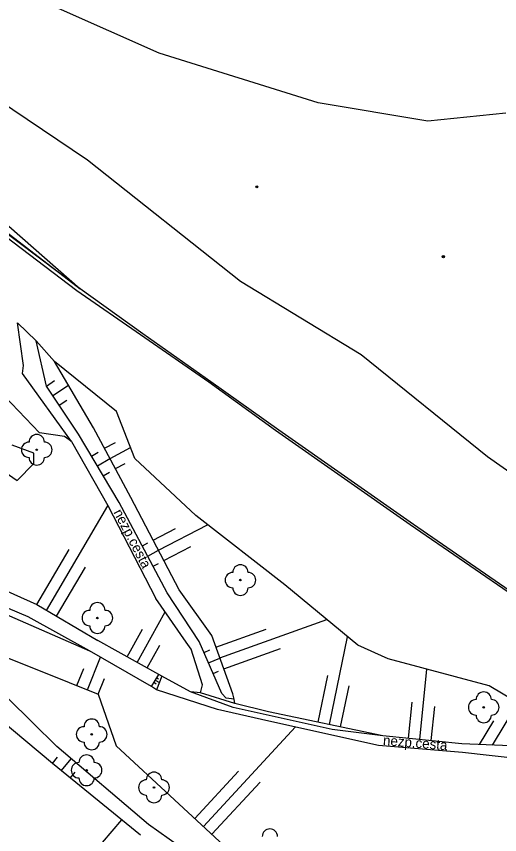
# Model space of a CAD drawing. Extents: x -639440 to -639026, y -1138850 to -1138262.
# Drawn here: x -639194.2 to -639162.7, y -1138656 to -1138602.7 of the extents above; entities that cross this region are included whole.
import ezdxf

# ---------------------------------------------------------------- set-up
doc = ezdxf.new("R2010")
doc.units = 0
for name, color, linetype in [('Vrstva 10', 7, 'Continuous'), ('Vrstva 11', 7, 'Continuous'), ('Vrstva 14', 7, 'Continuous'), ('Vrstva 15', 7, 'Continuous'), ('Vrstva 20', 7, 'Continuous'), ('Vrstva 22', 7, 'Continuous'), ('Vrstva 40', 7, 'Continuous'), ('Vrstva 7', 7, 'Continuous')]:
    doc.layers.add(name, color=color, linetype=linetype)

msp = doc.modelspace()

# ---------------------------------------------------------------- linework, layer by layer
at = {"layer": 'Vrstva 10'}
msp.add_line((-639192.91, -1138623.8), (-639194.14, -1138622.62), dxfattribs=at)
at = {"layer": 'Vrstva 11'}
for p, q in [((-639184.91, -1138605.05), (-639191.46, -1138602.15)), ((-639174.55, -1138608.29), (-639184.91, -1138605.05)), ((-639196.95, -1138607.03), (-639189.58, -1138612.02)), ((-639167.4, -1138609.48), (-639174.55, -1138608.29)), ((-639162.32, -1138608.96), (-639167.4, -1138609.48)), ((-639189.58, -1138612.02), (-639179.6, -1138619.92)), ((-639179.6, -1138619.92), (-639171.74, -1138624.69)), ((-639193.75, -1138625.41), (-639194.14, -1138622.62)), ((-639171.74, -1138624.69), (-639163.51, -1138631.34)), ((-639193.81, -1138625.92), (-639193.75, -1138625.41)), ((-639190.62, -1138630.37), (-639193.81, -1138625.92)), ((-639190.62, -1138630.37), (-639188.25, -1138634.54)), ((-639163.51, -1138631.34), (-639154.27, -1138637.86)), ((-639188.25, -1138634.54), (-639185.12, -1138640.58)), ((-639193.43, -1138641.79), (-639198.66, -1138639.56)), ((-639181.48, -1138643), (-639183.59, -1138640.03)), ((-639183.15, -1138643.44), (-639185.12, -1138640.58)), ((-639189.45, -1138644), (-639193.43, -1138641.79)), ((-639180.11, -1138646.79), (-639181.48, -1138643)), ((-639182.82, -1138643.89), (-639183.15, -1138643.44)), ((-639185.41, -1138646.32), (-639189.45, -1138644)), ((-639182.07, -1138646.22), (-639182.82, -1138643.89)), ((-639185.07, -1138646.54), (-639185.41, -1138646.32)), ((-639182.21, -1138646.74), (-639182.07, -1138646.22)), ((-639181.1, -1138647.81), (-639185.07, -1138646.54)), ((-639180.08, -1138647.68), (-639182.86, -1138646.67)), ((-639180.02, -1138647.15), (-639180.11, -1138646.79)), ((-639191.57, -1138650.23), (-639194.74, -1138647.11)), ((-639179.98, -1138647.42), (-639180.02, -1138647.15)), ((-639177.76, -1138648.57), (-639181.1, -1138647.81)), ((-639173.64, -1138649.12), (-639180.08, -1138647.68)), ((-639170.61, -1138650.17), (-639177.76, -1138648.57)), ((-639170.33, -1138649.53), (-639173.64, -1138649.12)), ((-639185.6, -1138655.32), (-639191.57, -1138650.23)), ((-639165.14, -1138650.62), (-639170.61, -1138650.17)), ((-639161, -1138651.09), (-639165.14, -1138650.62)), ((-639174.79, -1138662.91), (-639185.6, -1138655.32))]:
    msp.add_line(p, q, dxfattribs=at)
at = {"layer": 'Vrstva 14'}
for p, q in [((-639204.07, -1138608.17), (-639190.04, -1138620.41)), ((-639205.13, -1138608.87), (-639190.04, -1138620.41)), ((-639192.7, -1138629.79), (-639198.81, -1138623.41)), ((-639191.72, -1138625.14), (-639192.91, -1138623.8)), ((-639192.25, -1138626.75), (-639192.91, -1138623.8)), ((-639187.69, -1138628.41), (-639191.72, -1138625.14)), ((-639189.18, -1138629.46), (-639191.72, -1138625.14)), ((-639190.16, -1138629.89), (-639192.25, -1138626.75)), ((-639186.49, -1138631.47), (-639187.69, -1138628.41)), ((-639199.22, -1138629.4), (-639194.15, -1138632.91)), ((-639191.07, -1138630.04), (-639192.7, -1138629.79)), ((-639187.5, -1138634.34), (-639190.16, -1138629.89)), ((-639186.74, -1138634.01), (-639189.18, -1138629.46)), ((-639190.62, -1138630.37), (-639191.07, -1138630.04)), ((-639193.07, -1138631.11), (-639194.49, -1138630.6)), ((-639193.07, -1138631.79), (-639193.07, -1138631.11)), ((-639182.52, -1138635.19), (-639186.49, -1138631.47)), ((-639194.15, -1138632.91), (-639193.07, -1138631.79)), ((-639183.59, -1138640.03), (-639186.74, -1138634.01)), ((-639184.38, -1138640.21), (-639187.5, -1138634.34)), ((-639176.72, -1138639.69), (-639182.52, -1138635.19)), ((-639198.41, -1138638.5), (-639192.88, -1138640.99)), ((-639171.97, -1138643.62), (-639176.72, -1138639.69)), ((-639182.29, -1138643.39), (-639184.38, -1138640.21)), ((-639192.88, -1138640.99), (-639188.89, -1138643.33)), ((-639195, -1138641.56), (-639189.45, -1138644)), ((-639198.98, -1138642.76), (-639192.66, -1138645.31)), ((-639184.93, -1138645.53), (-639188.89, -1138643.33)), ((-639180.81, -1138646.77), (-639182.29, -1138643.39)), ((-639169.99, -1138644.52), (-639171.97, -1138643.62)), ((-639163.4, -1138646.27), (-639169.99, -1138644.52)), ((-639192.66, -1138645.31), (-639188.87, -1138646.82)), ((-639185.41, -1138646.32), (-639184.93, -1138645.53)), ((-639184.73, -1138645.65), (-639185.07, -1138646.54)), ((-639184.73, -1138645.65), (-639184.93, -1138645.53)), ((-639182.86, -1138646.67), (-639184.73, -1138645.65)), ((-639158.06, -1138649.5), (-639163.4, -1138646.27)), ((-639188.87, -1138646.82), (-639187.71, -1138650.18)), ((-639182.21, -1138646.74), (-639182.86, -1138646.67)), ((-639179.98, -1138647.42), (-639182.21, -1138646.74)), ((-639180.54, -1138647.08), (-639180.81, -1138646.77)), ((-639180.02, -1138647.15), (-639180.54, -1138647.08)), ((-639177.78, -1138647.98), (-639179.98, -1138647.42)), ((-639170.33, -1138649.53), (-639177.78, -1138647.98)), ((-639191.85, -1138651.33), (-639195.35, -1138648.43)), ((-639165.18, -1138650.05), (-639170.33, -1138649.53)), ((-639187.71, -1138650.18), (-639174.57, -1138662.33)), ((-639161.13, -1138650.22), (-639165.18, -1138650.05)), ((-639186.12, -1138656), (-639191.85, -1138651.33))]:
    msp.add_line(p, q, dxfattribs=at)
at = {"layer": 'Vrstva 15'}
for p, q in [((-639192.25, -1138626.75), (-639191.719, -1138626.397)), ((-639191.834, -1138627.374), (-639190.808, -1138626.691)), ((-639191.419, -1138627.999), (-639190.923, -1138627.669)), ((-639188.461, -1138630.802), (-639187.755, -1138630.423)), ((-639188.106, -1138631.463), (-639186.773, -1138630.748)), ((-639189.312, -1138631.308), (-639188.887, -1138631.054)), ((-639188.928, -1138631.952), (-639188.107, -1138631.461)), ((-639187.752, -1138632.123), (-639187.125, -1138631.787)), ((-639188.543, -1138632.595), (-639188.147, -1138632.359)), ((-639192.233, -1138641.37), (-639188.239, -1138634.56)), ((-639184.941, -1138637.449), (-639181.756, -1138635.783)), ((-639185.288, -1138636.784), (-639183.848, -1138636.031)), ((-639192.88, -1138640.99), (-639190.773, -1138637.398)), ((-639186, -1138637.162), (-639185.644, -1138636.973)), ((-639184.593, -1138638.114), (-639182.849, -1138637.201)), ((-639185.648, -1138637.824), (-639184.941, -1138637.448)), ((-639185.296, -1138638.486), (-639184.945, -1138638.299)), ((-639191.586, -1138641.749), (-639189.709, -1138638.548)), ((-639186.338, -1138644.748), (-639184.513, -1138641.462)), ((-639180.95, -1138644.465), (-639173.99, -1138641.949)), ((-639186.994, -1138644.383), (-639185.991, -1138642.578)), ((-639181.205, -1138643.76), (-639177.933, -1138642.577)), ((-639173.815, -1138648.805), (-639172.624, -1138643.079)), ((-639185.683, -1138645.112), (-639184.86, -1138643.631)), ((-639181.98, -1138644.099), (-639181.593, -1138643.929)), ((-639180.695, -1138645.171), (-639177.007, -1138643.837)), ((-639189.567, -1138646.542), (-639188.72, -1138644.419)), ((-639181.679, -1138644.786), (-639180.95, -1138644.466)), ((-639190.263, -1138646.265), (-639189.82, -1138645.153)), ((-639181.378, -1138645.473), (-639181.036, -1138645.323)), ((-639167.921, -1138649.773), (-639167.459, -1138645.192)), ((-639188.87, -1138646.82), (-639188.467, -1138645.808)), ((-639185.155, -1138645.901), (-639184.888, -1138646.064)), ((-639185.066, -1138645.754), (-639184.946, -1138645.827)), ((-639174.55, -1138648.652), (-639173.914, -1138645.595)), ((-639185.245, -1138646.048), (-639185.098, -1138646.138)), ((-639173.081, -1138648.958), (-639172.526, -1138646.289)), ((-639168.668, -1138649.698), (-639168.43, -1138647.348)), ((-639163.179, -1138650.134), (-639161.527, -1138647.403)), ((-639167.175, -1138649.849), (-639166.95, -1138647.618)), ((-639164.034, -1138650.098), (-639163.101, -1138648.556)), ((-639182.024, -1138655.437), (-639176.032, -1138648.957)), ((-639191.85, -1138651.33), (-639191.528, -1138650.935)), ((-639191.269, -1138651.804), (-639190.635, -1138651.027)), ((-639190.687, -1138652.278), (-639190.376, -1138651.896)), ((-639182.575, -1138654.928), (-639179.727, -1138651.848)), ((-639181.474, -1138655.946), (-639178.33, -1138652.546)), ((-639192.202, -1138660.692), (-639187.327, -1138655.016))]:
    msp.add_line(p, q, dxfattribs=at)
at = {"layer": 'Vrstva 20'}
for centre, radius in [((-639178.54, -1138613.77), 0.075), ((-639178.54, -1138613.77), 0.0204), ((-639166.39, -1138618.32), 0.075), ((-639166.39, -1138618.32), 0.0204)]:
    msp.add_circle(centre, radius, dxfattribs=at)
at = {"layer": 'Vrstva 22'}
for centre in [(-639192.88, -1138630.9), (-639179.61, -1138639.39), (-639188.93, -1138641.86), (-639163.76, -1138647.68), (-639189.3, -1138649.44), (-639189.63, -1138651.78), (-639185.24, -1138652.9)]:
    msp.add_circle(centre, 0.05, dxfattribs=at)
for centre, start, end in [((-639192.88, -1138630.4), 0, 180), ((-639193.38, -1138630.9), 90, 270), ((-639192.38, -1138630.9), 270, 90), ((-639192.88, -1138631.4), 180, 0), ((-639179.61, -1138638.89), 0, 180), ((-639180.11, -1138639.39), 90, 270), ((-639179.11, -1138639.39), 270, 90), ((-639179.61, -1138639.89), 180, 0), ((-639188.93, -1138641.36), 0, 180), ((-639189.43, -1138641.86), 90, 270), ((-639188.43, -1138641.86), 270, 90), ((-639188.93, -1138642.36), 180, 0), ((-639163.76, -1138647.18), 0, 180), ((-639164.26, -1138647.68), 90, 270), ((-639163.26, -1138647.68), 270, 90), ((-639189.3, -1138648.94), 0, 180), ((-639163.76, -1138648.18), 180, 0), ((-639189.8, -1138649.44), 90, 270), ((-639188.8, -1138649.44), 270, 90), ((-639189.3, -1138649.94), 180, 0), ((-639190.13, -1138651.78), 90, 270), ((-639189.63, -1138651.28), 0, 180), ((-639189.13, -1138651.78), 270, 90), ((-639189.63, -1138652.28), 180, 0), ((-639185.24, -1138652.4), 0, 180), ((-639185.74, -1138652.9), 90, 270), ((-639184.74, -1138652.9), 270, 90), ((-639185.24, -1138653.4), 180, 0), ((-639177.69, -1138656.1), 0, 180)]:
    msp.add_arc(centre, 0.5, start, end, dxfattribs=at)
at = {"layer": 'Vrstva 7'}
for p, q in [((-639190.04, -1138620.41), (-639216.21, -1138600.66)), ((-639190.26, -1138620.55), (-639201.16, -1138612.3)), ((-639190.04, -1138620.41), (-639200.96, -1138612.21)), ((-639186.12, -1138623.42), (-639190.26, -1138620.55)), ((-639185.96, -1138623.34), (-639190.04, -1138620.41)), ((-639181.66, -1138626.5), (-639186.12, -1138623.42)), ((-639181.53, -1138626.48), (-639185.96, -1138623.34)), ((-639177.33, -1138629.64), (-639181.66, -1138626.5)), ((-639177.11, -1138629.62), (-639181.53, -1138626.48)), ((-639168.55, -1138635.78), (-639177.33, -1138629.64)), ((-639168.33, -1138635.77), (-639177.11, -1138629.62)), ((-639159.61, -1138641.94), (-639168.55, -1138635.78)), ((-639159.45, -1138641.91), (-639168.33, -1138635.77))]:
    msp.add_line(p, q, dxfattribs=at)

# ---------------------------------------------------------------- texts
at = {"layer": 'Vrstva 40'}
for rotation, p in [(297.3937, (-639187.897, -1138634.966)), (355.297, (-639170.339, -1138650.134))]:
    msp.add_text('nezp.cesta', height=0.65, rotation=rotation, dxfattribs=at).set_placement(p)

doc.saveas('drawing.dxf')
